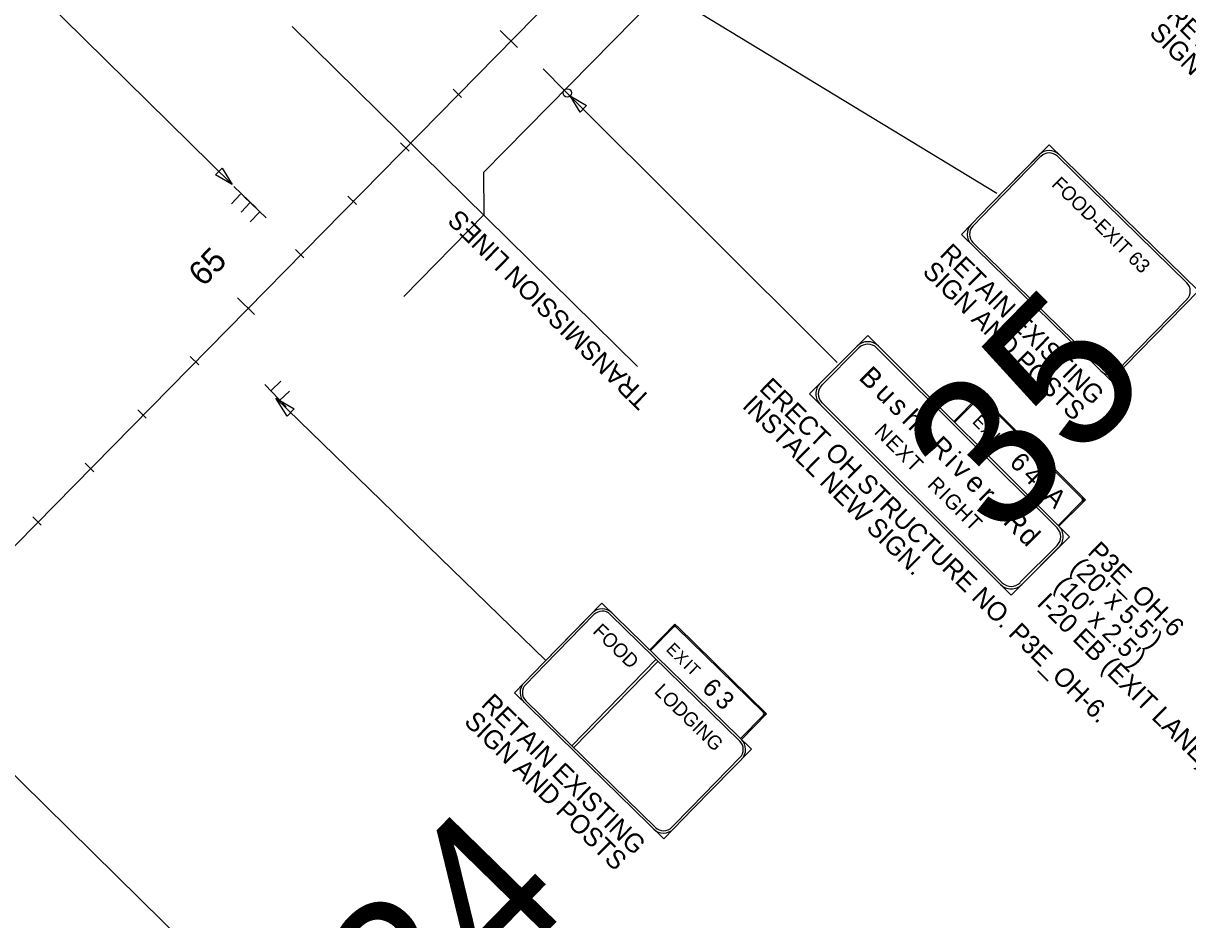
# Model space of a CAD drawing. Extents: x -5665 to 1997148, y 4 to 827579.
# Drawn here: x 1958925 to 1960479, y 794938 to 796134 of the extents above; entities that cross this region are included whole.
import ezdxf

# ---------------------------------------------------------------- set-up
doc = ezdxf.new("R2010")
doc.units = 0
for name, color, linetype in [('Default', 7, 'Continuous'), ('RD_HC_CL_Rel', 7, 'Continuous'), ('RD_HC_Data_Tic_Rel', 7, 'Continuous'), ('RD_HC_TX_Rel_Sta50', 7, 'Continuous'), ('RD_PD_Final_TX', 7, 'Continuous'), ('RD_SHT_TX', 7, 'Continuous'), ('TR SN EXTRUDED PANEL SIGNS- MOUNTED OVERHEAD', 7, 'Continuous')]:
    doc.layers.add(name, color=color, linetype=linetype)

msp = doc.modelspace()

# ---------------------------------------------------------------- linework, layer by layer
at = {"layer": 'Default'}
for p, q in [((1959539.4, 795935.2), (1960207.3, 796614.2)), ((1959539.9, 795878.6), (1959539.4, 795935.2)), ((1959432.5, 795769.5), (1959539.9, 795878.6))]:
    msp.add_line(p, q, dxfattribs=at)
at = {"layer": 'RD_HC_CL_Rel'}
msp.add_line((1957622, 794124.4), (1963740.1, 800343.8), dxfattribs=at)
at = {"layer": 'RD_HC_Data_Tic_Rel'}
for p, q in [((1959584, 796101.7), (1959561.2, 796124.2)), ((1959509.6, 796034.7), (1959498.2, 796045.9)), ((1959439.5, 795963.4), (1959428, 795974.6)), ((1959369.3, 795892.1), (1959357.9, 795903.3)), ((1959299.2, 795820.8), (1959287.8, 795832)), ((1959233.3, 795745.3), (1959210.5, 795767.7)), ((1959158.9, 795678.2), (1959147.5, 795689.4)), ((1959088.8, 795606.9), (1959077.4, 795618.2)), ((1959018.7, 795535.6), (1959007.3, 795546.9)), ((1958948.6, 795464.4), (1958937.2, 795475.6))]:
    msp.add_line(p, q, dxfattribs=at)
at = {"layer": 'RD_PD_Final_TX'}
msp.add_lwpolyline([(1959286.2, 795619.7), (1959276.6, 795609.9), (1959261.7, 795634)], close=True, dxfattribs=at)
at = {"layer": 'RD_SHT_TX'}
msp.add_line((1959283.6, 796129.4), (1959744.5, 795676), dxfattribs=at)
at = {"layer": 'TR SN EXTRUDED PANEL SIGNS- MOUNTED OVERHEAD'}
for p, q in [((1959203.3, 795918.8), (1958867.7, 796249.1)), ((1959816.3, 796154.5), (1960224, 795907.2)), ((1959618.5, 796073.1), (1959647.4, 796043.6)), ((1959640.7, 796050.6), (1960010.8, 795681.3)), ((1959202.3, 795893), (1959214.7, 795905.8)), ((1959235.3, 795887.5), (1959205.8, 795916)), ((1959248.6, 795874.5), (1959219, 795903)), ((1959215.2, 795881.9), (1959227.6, 795894.7)), ((1959227.4, 795869.2), (1959239.8, 795882)), ((1959247, 795652.1), (1959275.3, 795622.4)), ((1959268.4, 795656.5), (1959255.5, 795644.2)), ((1959280, 795643.3), (1959267.1, 795631)), ((1959622, 795283.8), (1959261.7, 795634)), ((1958818.9, 795223.1), (1959187.5, 794860.5))]:
    msp.add_line(p, q, dxfattribs=at)
for points in [[(1959676.3, 796024), (1959667.6, 796015.2), (1959654.3, 796037)], [(1959181.3, 795931.8), (1959190, 795940.6), (1959203.3, 795918.8)]]:
    msp.add_lwpolyline(points, close=True, dxfattribs=at)
for points in [[(1960414.9, 795697.1), (1960492.9, 795776.9), (1960293.6, 795971.8), (1960215.6, 795892.1), (1960215.6, 795892.1)], [(1960215.6, 795892.1), (1960280.6, 795958.5)], [(1960282.8, 795956.4), (1960217.8, 795889.9)], [(1960477.4, 795787.6), (1960304.7, 795956.6)], [(1960215.6, 795892.1), (1960176.6, 795852.2), (1960176.6, 795852.2)], [(1960217.8, 795889.9), (1960191.8, 795863.3)], [(1960176.6, 795852.2), (1960375.9, 795657.3), (1960414.9, 795697.1)], [(1960192, 795841.4), (1960364.8, 795672.5)], [(1960412.7, 795699.3), (1960477.7, 795765.7)], [(1959974, 795639.5), (1960243, 795371.1), (1960320.7, 795449), (1960051.7, 795717.4), (1959974, 795639.5), (1959974, 795639.5), (1959974, 795639.5)], [(1959988.1, 795653.7), (1960037.6, 795703.2)], [(1960039.9, 795700.9), (1959990.5, 795651.3)], [(1960039.9, 795700.9), (1960039.9, 795700.9), (1960039.9, 795700.9)], [(1960304.2, 795460.8), (1960063.5, 795700.9)], [(1960065.8, 795703.3), (1960306.5, 795463.1)], [(1960386.7, 795672.7), (1960412.7, 795699.3)], [(1960306.8, 795462.9), (1960342.1, 795498.3), (1960201.8, 795638.2), (1960166.5, 795602.8), (1960166.5, 795602.8), (1960166.5, 795602.8)], [(1960228.9, 795385.3), (1959988.2, 795625.4)], [(1959990.5, 795627.8), (1960231.2, 795387.6)], [(1959990.5, 795627.8), (1959990.5, 795627.8), (1959990.5, 795627.8)], [(1960166.5, 795602.8), (1960198.3, 795634.7)], [(1960199.5, 795633.5), (1960167.7, 795601.6)], [(1960199.5, 795633.5), (1960199.5, 795633.5), (1960199.5, 795633.5)], [(1960337.4, 795500.6), (1960204.2, 795633.5)], [(1960205.4, 795634.7), (1960338.6, 795501.8)], [(1960337.4, 795500.6), (1960337.4, 795500.6), (1960337.4, 795500.6)], [(1960305.6, 795464.1), (1960337.4, 795495.9)], [(1960338.6, 795494.7), (1960306.8, 795462.9)], [(1960304.5, 795460.5), (1960304.5, 795460.5), (1960304.5, 795460.5)], [(1960305.6, 795464.1), (1960305.6, 795464.1), (1960305.6, 795464.1)], [(1960254.8, 795387.7), (1960304.2, 795437.2)], [(1960306.6, 795434.9), (1960257.1, 795385.3)], [(1960254.8, 795387.7), (1960254.8, 795387.7), (1960254.8, 795387.7)], [(1959818.3, 795085.8), (1959896.3, 795165.5), (1959696.9, 795360.4), (1959618.9, 795280.7), (1959618.9, 795280.7)], [(1959618.9, 795280.7), (1959683.9, 795347.2)], [(1959686.1, 795345), (1959621.2, 795278.5)], [(1959880.8, 795176.3), (1959708, 795345.2)], [(1959795.7, 795330.9), (1959794.2, 795332.4), (1959760.7, 795298.1), (1959760.7, 795298.1)], [(1959792, 795327.8), (1959761.8, 795297)], [(1959911.9, 795215), (1959796.5, 795327.9)], [(1959883, 795178.5), (1959916.5, 795212.8), (1959797.6, 795329)], [(1959618.9, 795280.7), (1959580, 795240.8), (1959580, 795240.8)], [(1959656.7, 795170.1), (1959769, 795285)], [(1959659.2, 795167.7), (1959771.5, 795282.5)], [(1959621.2, 795278.5), (1959595.2, 795252)], [(1959580, 795240.8), (1959779.3, 795045.9), (1959818.3, 795085.8)], [(1959595.4, 795230.1), (1959768.2, 795061.1)], [(1959881.8, 795179.6), (1959912, 795210.5)], [(1959816.1, 795087.9), (1959881, 795154.4)], [(1959790.1, 795061.4), (1959816.1, 795087.9)]]:
    msp.add_lwpolyline(points, dxfattribs=at)
msp.add_circle((1959650.5, 796041), 5.54, dxfattribs=at)
for centre, radius, start, end in [((1960293.8, 795945.5), 18.6, 45.6379, 135.6375), ((1960293.8, 795945.5), 15.5, 45.6379, 135.6375), ((1960202.9, 795852.5), 18.6, 135.6375, 225.6377), ((1960202.9, 795852.5), 15.5, 135.6375, 225.6377), ((1960466.6, 795776.6), 15.5, 315.6376, 45.6379), ((1960051.7, 795689.1), 20, 45.0679, 135.0675), ((1960051.7, 795689.1), 16.7, 45.0679, 135.0675), ((1960375.6, 795683.6), 18.6, 225.6377, 315.6379), ((1960375.6, 795683.6), 15.5, 225.6377, 315.6379), ((1960002.3, 795639.6), 20, 135.0675, 225.0677), ((1960002.3, 795639.6), 16.7, 135.0675, 225.0677), ((1960201.9, 795631.2), 5, 45.0679, 135.0675), ((1960201.9, 795631.2), 3.33, 45.0679, 135.0675), ((1960335.1, 795498.3), 3.33, 315.0677, 45.0679), ((1960335.1, 795498.3), 5, 315.0677, 45.0679), ((1960292.4, 795449), 16.7, 315.0677, 45.0679), ((1960292.4, 795449), 20, 315.0677, 45.0679), ((1960243, 795399.4), 20, 225.0677, 315.0679), ((1960243, 795399.4), 16.7, 225.0677, 315.0679), ((1959697.2, 795334.2), 18.6, 45.6379, 135.6375), ((1959697.2, 795334.2), 15.5, 45.6379, 135.6375), ((1959794.3, 795325.6), 4.8, 45.6379, 135.6375), ((1959794.3, 795325.6), 3.2, 45.6379, 135.6375), ((1959606.2, 795241.1), 18.6, 135.6375, 225.6377), ((1959606.2, 795241.1), 15.5, 135.6375, 225.6377), ((1959909.7, 795212.7), 3.2, 315.6376, 45.6379), ((1959909.7, 795212.7), 4.8, 315.6376, 45.6379), ((1959870, 795165.2), 15.5, 315.6376, 45.6379), ((1959870, 795165.2), 18.6, 315.6376, 45.6379), ((1959779, 795072.2), 18.6, 225.6377, 315.6379), ((1959779, 795072.2), 15.5, 225.6377, 315.6379)]:
    msp.add_arc(centre, radius, start, end, dxfattribs=at)

# ---------------------------------------------------------------- texts
at = {"layer": 'RD_HC_TX_Rel_Sta50'}
msp.add_text('65', height=32, rotation=45.4705, dxfattribs=at).set_placement((1959164.8, 795781.3))
at = {"layer": 'RD_SHT_TX'}
for s, height, rotation, p in [('TRANSMISSION LINES', 25, 135.4705, (1959763.5, 795634.2)), ('35', 200, 45.6376, (1960226.9, 795440.5)), ('34', 200, 45.6376, (1959452, 794746.6))]:
    msp.add_text(s, height=height, rotation=rotation, dxfattribs=at).set_placement(p)
at = {"layer": 'TR SN EXTRUDED PANEL SIGNS- MOUNTED OVERHEAD'}
for s, height, rotation, p in [('RETAIN EXISTING', 25, 315.6376, (1960448.8, 796142.8)), ('SIGN AND POSTS', 25, 315.6376, (1960426.1, 796119.5)), ('FOOD-EXIT 63', 18.587, 315.6376, (1960295.9, 795917.8)), ('RETAIN EXISTING', 25, 315.6376, (1960146.2, 795824.4)), ('SIGN AND POSTS', 25, 315.6376, (1960123.4, 795801.1)), ('B', 26.7, 315.0677, (1960038.5, 795659.9)), ('ERECT OH STRUCTURE NO. P3E_OH-6.', 25, 315.4705, (1959905.6, 795645.4)), ('INSTALL NEW SIGN.', 25, 315.4705, (1959882.8, 795622.2)), ('u', 26.7, 315.0677, (1960060.3, 795638.2)), ('s', 26.7, 315.0677, (1960077.9, 795620.6)), ('h', 26.7, 315.0677, (1960095.8, 795602.7)), ('E', 16.7, 315.0677, (1960190.3, 795601.5)), ('N', 20, 315.0677, (1960059.1, 795587.6)), ('X', 16.7, 315.0677, (1960201.5, 795590.3)), ('E', 20, 315.0677, (1960074, 795572.7)), ('R', 26.7, 315.0677, (1960131.7, 795566.9)), ('I', 16.7, 315.0677, (1960214.1, 795577.7)), ('T', 16.7, 315.0677, (1960218.9, 795572.9)), ('X', 20, 315.0677, (1960087.4, 795559.3)), ('T', 20, 315.0677, (1960101.7, 795545.1)), ('i', 26.7, 315.0677, (1960153.1, 795545.6)), ('6', 25, 315.0677, (1960239.5, 795546.5)), ('v', 26.7, 315.0677, (1960162, 795536.8)), ('R', 20, 315.0677, (1960129.9, 795517)), ('e', 26.7, 315.0677, (1960179.9, 795518.8)), ('4', 25, 315.0677, (1960257.2, 795528.8)), ('I', 20, 315.0677, (1960144.8, 795502.1)), ('r', 26.7, 315.0677, (1960198.1, 795500.7)), ('G', 20, 315.0677, (1960151.3, 795495.7)), ('A', 25, 315.0677, (1960285.4, 795500.8)), ('H', 20, 315.0677, (1960166.2, 795480.8)), ('R', 26.7, 315.0677, (1960231, 795467.8)), ('T', 20, 315.0677, (1960180.4, 795466.6)), ('d', 26.7, 315.0677, (1960251, 795448)), ('P3E_OH-6', 25, 315.3323, (1960343.8, 795427.1)), ("(20' x 5.5')", 25, 315.3323, (1960320.8, 795406.1)), ("(10' x 2.5')", 25, 315.3323, (1960298.8, 795381.7)), ('I-20 EB (EXIT LANE)', 25, 315.3323, (1960275.9, 795358.6)), ('FOOD', 18.59, 315.6376, (1959683.6, 795321.7)), ('E', 16, 315.6376, (1959781.3, 795297.7)), ('X', 16, 315.6376, (1959792.2, 795287.1)), ('I', 16, 315.6376, (1959804.4, 795275.1)), ('T', 16, 315.6376, (1959809.1, 795270.6)), ('LODGING', 18.59, 315.6376, (1959765.6, 795241.5)), ('6', 24, 315.6376, (1959829.1, 795245.5)), ('RETAIN EXISTING', 25, 315.6376, (1959534.4, 795224.1)), ('3', 24, 315.6376, (1959846.3, 795228.6)), ('SIGN AND POSTS', 25, 315.6376, (1959511.6, 795200.8))]:
    msp.add_text(s, height=height, rotation=rotation, dxfattribs=at).set_placement(p)

doc.saveas('drawing.dxf')
